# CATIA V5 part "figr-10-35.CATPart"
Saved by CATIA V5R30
Part number: Part1
Bounding box of the stored display mesh (mm): x -80 to 120, y 0 to 190, z 0 to 170
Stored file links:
  D:\PROJECTS\CATIA V56R 2020\Resources\Parts File\c10_catia_v5_6r2020_prt\figr-10-35.CATPart
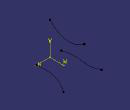
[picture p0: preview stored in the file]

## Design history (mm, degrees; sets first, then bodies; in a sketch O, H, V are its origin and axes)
Set1
  Sketch1 on xy-plane, origin (0, 0, 0), H (1, 0, 0), V (0, 1, 0)
    spline S1 through (-60, 0) (-70, 70) (-70, 170) (-80, 190)
  Sketch2 on yz-plane, origin (0, 0, 0), H (0, 1, 0), V (0, 0, 1)
    spline S1 through (0, 170) (100, 120) (180, 150)
  Sketch3 on xy-plane, origin (0, 0, 0), H (1, 0, 0), V (0, 1, 0)
    spline S1 through (70, 0) (70, 80) (120, 190)
Body1 (main body)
